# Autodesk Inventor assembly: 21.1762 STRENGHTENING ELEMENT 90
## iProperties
Created: 2007-04
Part Number: 21.1762 STRENGHTENING ELEMENT 90
Document SubType Name: Assembly
Designer: Andy Moles
Author: Andy Moles
